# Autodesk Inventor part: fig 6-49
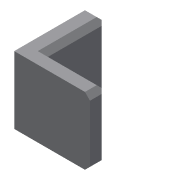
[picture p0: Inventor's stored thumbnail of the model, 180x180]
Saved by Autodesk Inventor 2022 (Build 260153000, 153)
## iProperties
Created: 2009-09
Part Number: fig 6-49
Document SubType Name: Modeling
Designer: Sham
Density: 1 g/cm^3
Material: Generic
Appearance: Default
Author: Sham
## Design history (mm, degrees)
sketch "Sketch1"
  geometry: L1 (1.789, 30)-(1.789, -5); L2 (1.789, -5)-(36.789, -5); L3 (36.789, -5)-(36.789, -15); L4 (36.789, -15)-(-8.211, -15); L5 (-8.211, -15)-(-8.211, 30); L6 (-8.211, 30)-(1.789, 30)
  constraints: 12 end point, 6 perpendicular
  dimensions: "d0" = 10 distance of L5.end L1.start; "d1" = 35 distance of L1.start L1.end; "d2" = 45 distance of L3.end L4.end; "d3" = 10 distance of L2.end L3.end (derived)
extrude "Extrusion1" new body sketch "Sketch1" distance "d4" = 40; taper "d5" = 0 deg
chamfer "Chamfer1" distance "d6" = 3; stored, may be unused: second distance "d7" = 2, angle "d8" = 45 deg
body "Solid1"
other parameters: "d1" = 35
